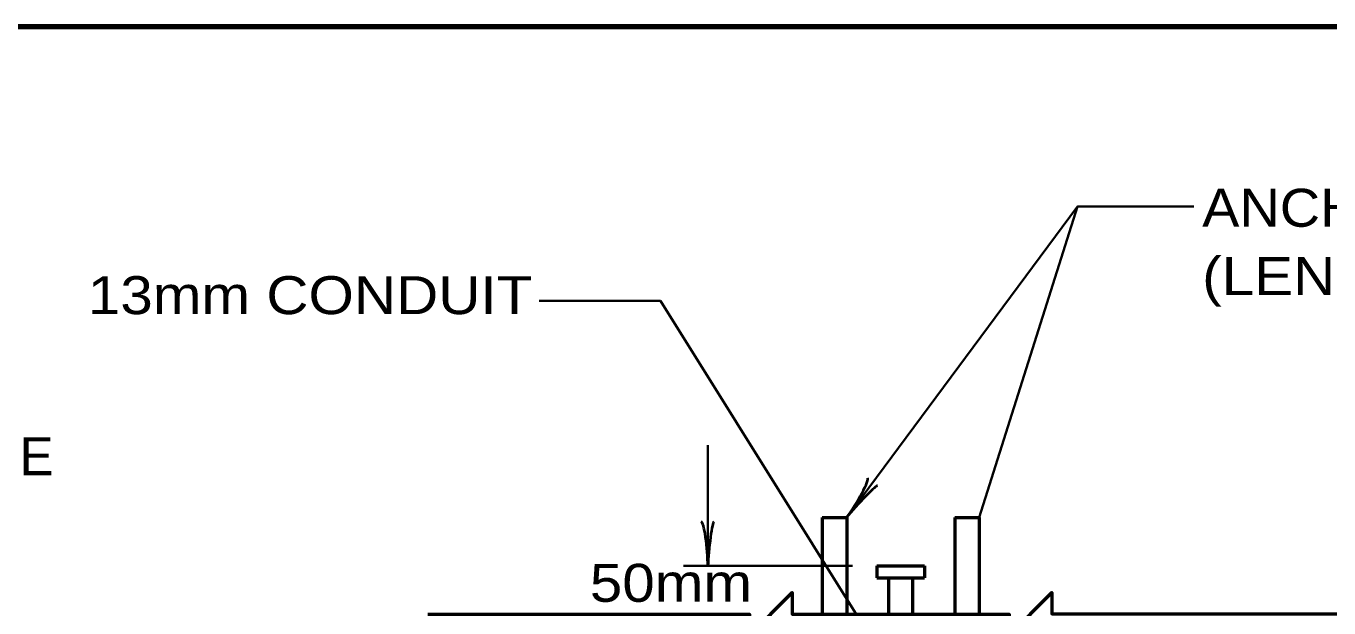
# Model space of a CAD drawing. Extents: x -39 to 816, y -16 to 528.
# Drawn here: x 387.3 to 490.2, y 475.9 to 521.9 of the extents above; entities that cross this region are included whole.
import ezdxf

# ---------------------------------------------------------------- set-up
doc = ezdxf.new("R2010")
doc.units = 0
doc.header["$LTSCALE"] = 0.97
doc.layers.add('1', color=7, linetype='Continuous', lineweight=35)

msp = doc.modelspace()

# ---------------------------------------------------------------- linework, layer by layer
at = {"layer": '1'}
for p, q in [((452.0966, 483.0279), (470.3366, 507.6039)), ((441.1286, 479.2119), (441.1286, 488.7399)), ((452.5526, 479.2119), (439.2086, 479.2119))]:
    msp.add_line(p, q, dxfattribs=at)
at = {"layer": '1', "lineweight": 53}
for p, q in [((450.1526, 483.0279), (450.1526, 432.0759)), ((450.1526, 483.0279), (452.0966, 483.0279)), ((452.0966, 483.0279), (452.0966, 432.0759)), ((460.6406, 483.0279), (460.6406, 432.0759)), ((460.6406, 483.0279), (462.5606, 483.0279)), ((462.5606, 483.0279), (462.5606, 432.0759)), ((454.4726, 479.2119), (458.2406, 479.2119)), ((454.4726, 479.2119), (454.4726, 478.2519)), ((458.2406, 479.2119), (458.2406, 478.2519)), ((454.4726, 478.2519), (458.2406, 478.2519)), ((455.4086, 478.2519), (455.4086, 435.8919)), ((457.3046, 478.2519), (457.3046, 435.8919))]:
    msp.add_line(p, q, dxfattribs=at)
at = {"layer": '1', "lineweight": 158}
msp.add_lwpolyline([(809.7034, 521.852), (18.0034, 521.752), (18.1034, -4.248)], dxfattribs=at)
at = {"layer": '1'}
for points in [[(462.5606, 483.0279), (470.3366, 507.6039), (479.5046, 507.6039)], [(455.4086, 471.3159), (437.3846, 500.1399), (427.8086, 500.1399)]]:
    msp.add_lwpolyline(points, dxfattribs=at)
at = {"layer": '1', "lineweight": 53}
msp.add_lwpolyline([(419.0094, 475.3959), (444.4166, 475.3959), (444.4166, 473.7159), (447.7766, 477.0999), (447.7766, 475.3959), (464.9366, 475.3959), (464.9366, 473.7159), (468.2966, 477.0999), (468.2966, 475.4199), (493.9107, 475.4199)], dxfattribs=at)
at = {"layer": '1', "lineweight": 40}
for centre, major_axis, ratio, start_param, end_param in [((452.6068, 484.2845), (-1.1367, -1.8464), 0.122415, 0.89635335, 3.14159265), ((452.6068, 484.2845), (-1.1367, -1.8464), 0.122415, 0.89635335, 3.14159265), ((453.1017, 483.9609), (1.4377, 1.5786), 0.07063, 6.28230741, 8.55970261), ((453.1017, 483.9609), (1.4377, 1.5786), 0.07063, 6.28230741, 8.55970261), ((440.7916, 480.5278), (0.1889, -2.16), 0.122415, 0.89635335, 3.14159265), ((440.7916, 480.5278), (0.1889, -2.16), 0.122415, 0.89635335, 3.14159265), ((441.3818, 480.5632), (-0.2125, -2.1246), 0.07063, 3.14071475, 5.41810995), ((441.3818, 480.5632), (-0.2125, -2.1246), 0.07063, 3.14071475, 5.41810995)]:
    msp.add_ellipse(centre, major_axis=major_axis, ratio=ratio, start_param=start_param, end_param=end_param, dxfattribs=at)

# ---------------------------------------------------------------- texts
at = {"layer": '1'}
for s, width, p in [('ANCHOR BOLTS', 1.1, (480.1766, 505.9959)), ("(LENGTH AS REQ'D.)", 1.15, (480.1766, 500.5959)), ('13mm CONDUIT', 1.15, (392.1462, 499.092)), ('50mm', 1.15, (431.8018, 476.3643))]:
    msp.add_text(s, height=3, dxfattribs=dict(at, width=width)).set_placement(p)
msp.add_text('POLE', height=3, dxfattribs=at).set_placement((378.7323, 486.3702))

doc.saveas('drawing.dxf')
